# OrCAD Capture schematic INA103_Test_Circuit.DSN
size A; title: Low Noise, Low Distortion INSTRUMENTATION AMPLIFIER; rev: 1.1; note: Datasheet: SBOS003 EVM: N/A
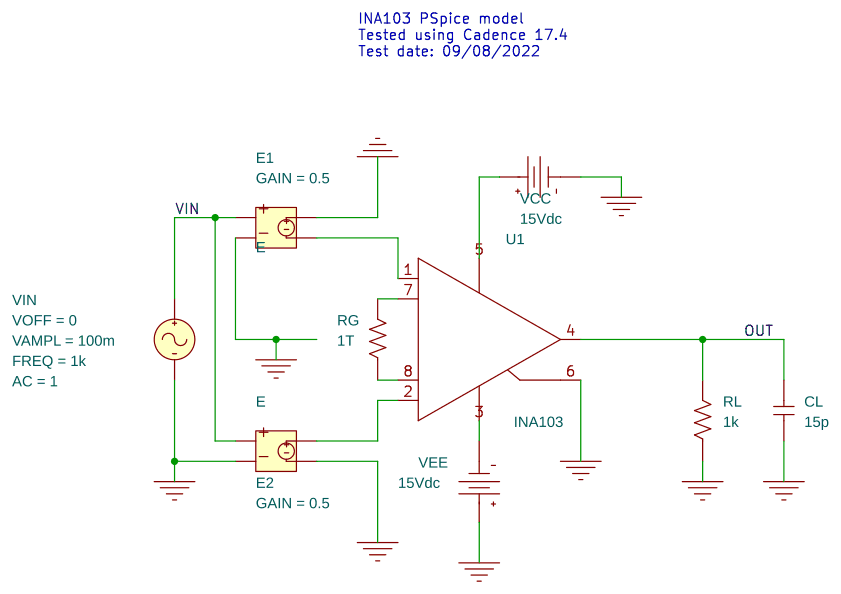
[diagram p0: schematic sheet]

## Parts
CL  15p  [RAD/CK05]
E1  E
E2  E
RG  1T  [AX/RC05]
RL  1k  [AX/RC05]
U1  INA103
VCC  VDC
VEE  VDC
VIN  VSIN

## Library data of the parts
CL = C
E1 E2 = E: GAIN: 0.5
RG RL = R
U1 = INA103
VCC VEE = VDC: DC: 15Vdc
VIN = VSIN: AC: 1; FREQ: 1k; VAMPL: 100m; VOFF: 0

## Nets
VIN: E1.1 E2.1 VIN.1(+)
0: CL.1 E1.2 E1.3 E2.2 E2.4 RL.1 U1.6(REF) VCC.1(-) VEE.0(+) VIN.2(-)
OUT: CL.2 RL.2 U1.4(OUT)
N11906: U1.5(V+) VCC.0(+)
N12274: RG.2 U1.7(RG+)
N12280: RG.1 U1.8(RG-)
N12286: E2.3 U1.2(+)
N24248: U1.3(V-) VEE.1(-)
N26159: E1.4 U1.1(-)

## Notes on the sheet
- INA103 PSpice model
  Tested using Cadence 17.4
  Test date: 09/08/2022
